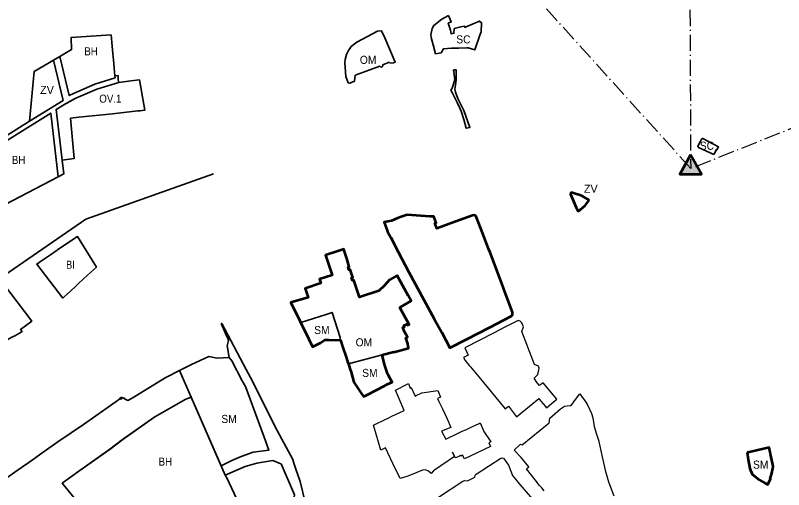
# Model space of a CAD drawing. Extents: x -650276 to -642489, y -1074311 to -1066658.
# Drawn here: x -648072 to -646929, y -1071077 to -1070373 of the extents above; entities that cross this region are included whole.
import ezdxf

# ---------------------------------------------------------------- set-up
doc = ezdxf.new("R2010")
doc.units = 0
doc.header["$LTSCALE"] = 4.8
doc.header["$PDMODE"] = 32
doc.header["$PDSIZE"] = 2.4
doc.linetypes.add('DOT_DASHED', pattern=[7.7, 5, -1.2, 0.3, -1.2])
for name, color, linetype, lineweight in [('1', 7, 'Continuous', 35), ('11', 7, 'Continuous', 35), ('12', 7, 'Continuous', 35), ('15', 7, 'Continuous', 35), ('17', 7, 'Continuous', 35), ('18', 7, 'Continuous', 35), ('2', 7, 'Continuous', 35), ('40', 7, 'Continuous', 35), ('54', 7, 'Continuous', 35), ('55', 7, 'Continuous', 53), ('60', 7, 'Continuous', 53), ('61', 7, 'Continuous', 25)]:
    doc.layers.add(name, color=color, linetype=linetype, lineweight=lineweight)
doc.layers.add('62', color=7, linetype='Continuous')
doc.layers.add('63', color=7, linetype='Continuous')

msp = doc.modelspace()

# ---------------------------------------------------------------- hatches: boundary and pattern name
at = {"layer": '55'}
msp.add_hatch(color=256, dxfattribs=at).paths.add_polyline_path([(-647067.857, -1070579.969), (-647083.808, -1070608.615), (-647051.424, -1070608.615)])

# ---------------------------------------------------------------- linework, layer by layer
at = {"layer": '1'}
for points in [[(-647991.539, -1070492.016), (-647985.19, -1070488.804), (-647953.251, -1070475.276), (-647923.247, -1070465.749), (-647923.53, -1070462.75), (-647924.63, -1070451.09), (-647925.5, -1070439.63), (-647926.53, -1070429.76), (-647927.67, -1070418.74), (-647929.24, -1070401.97), (-647988.86, -1070405.95), (-647988.11, -1070423.93), (-648005.668, -1070434.145)], [(-648098.637, -1070659.682), (-648007.838, -1070612.851), (-648019, -1070518), (-648135.47, -1070590.61), (-648105.98, -1070645.91)], [(-648001.922, -1071067.83), (-647977.41, -1071049.74), (-647930.7, -1071017.18), (-647911.838, -1071002.919), (-647864.03, -1070969.3), (-647864.03, -1070969.3), (-647818.33, -1070942.91), (-647810.243, -1070939.825), (-647759.52, -1071055.67), (-647757.19, -1071059.66), (-647742.64, -1071090.72), (-647726.74, -1071122.48), (-647742.35, -1071129.43), (-647775.982, -1071148.001), (-647775.982, -1071148.001), (-647875.939, -1071221.104)]]:
    msp.add_lwpolyline(points, close=True, dxfattribs=at)
at = {"layer": '11'}
msp.add_lwpolyline([(-647927.14, -1070519), (-647889.27, -1070514.92), (-647886.09, -1070514.58), (-647879.89, -1070513.91), (-647879.16, -1070513.83), (-647887.08, -1070468.54), (-647899.87, -1070470.04), (-647917.98, -1070472.47), (-647950.48, -1070482.79), (-647981.81, -1070496.06), (-647990.295, -1070500.352), (-647999.756, -1070505.655), (-648010.831, -1070512.588), (-648002, -1070588), (-647984.03, -1070585.46), (-647989.5, -1070525.73), (-647977.41, -1070524.43)], close=True, dxfattribs=at)
at = {"layer": '12'}
msp.add_lwpolyline([(-647515.73, -1070442.32), (-647514.23, -1070444.18), (-647509.22, -1070443.62), (-647506.95, -1070442.71), (-647522.54, -1070406.51), (-647527.1, -1070395.72), (-647533.1, -1070396.26), (-647564.01, -1070412.59), (-647572.37, -1070419.41), (-647576.48, -1070425.09), (-647579.22, -1070431.05), (-647581.04, -1070438.4), (-647581.54, -1070443.7), (-647580.1, -1070463.69), (-647576.92, -1070473), (-647574.28, -1070473.46), (-647567.32, -1070470.66), (-647566.55, -1070462.22), (-647565.11, -1070461.12), (-647529.74, -1070448.27), (-647528.28, -1070449.87), (-647525.54, -1070448.89), (-647525.45, -1070446.21)], close=True, dxfattribs=at)
msp.add_lwpolyline([(-647515.73, -1070442.32), (-647514.23, -1070444.18), (-647509.22, -1070443.62), (-647506.95, -1070442.71), (-647522.54, -1070406.51), (-647527.1, -1070395.72), (-647533.1, -1070396.26), (-647564.01, -1070412.59), (-647572.37, -1070419.41), (-647576.48, -1070425.09), (-647579.22, -1070431.05), (-647581.04, -1070438.4), (-647581.54, -1070443.7), (-647580.1, -1070463.69), (-647576.92, -1070473), (-647574.28, -1070473.46), (-647567.32, -1070470.66), (-647566.55, -1070462.22), (-647565.11, -1070461.12), (-647529.74, -1070448.27), (-647528.28, -1070449.87), (-647525.54, -1070448.89), (-647525.45, -1070446.21)], close=True, dxfattribs=at)
msp.add_lwpolyline([(-647515.73, -1070442.32), (-647514.23, -1070444.18), (-647509.22, -1070443.62), (-647506.95, -1070442.71), (-647522.54, -1070406.51), (-647527.1, -1070395.72), (-647533.1, -1070396.26), (-647564.01, -1070412.59), (-647572.37, -1070419.41), (-647576.48, -1070425.09), (-647579.22, -1070431.05), (-647581.04, -1070438.4), (-647581.54, -1070443.7), (-647580.1, -1070463.69), (-647576.92, -1070473), (-647574.28, -1070473.46), (-647567.32, -1070470.66), (-647566.55, -1070462.22), (-647565.11, -1070461.12), (-647529.74, -1070448.27), (-647528.28, -1070449.87), (-647525.54, -1070448.89), (-647525.45, -1070446.21)], close=True, dxfattribs=at)
for points in [[(-647569.92, -1070762.24), (-647573.88, -1070750.25), (-647575.58, -1070750.83), (-647576.81, -1070746.86), (-647575.09, -1070746.33), (-647578.79, -1070734.33), (-647583.38, -1070720.9), (-647583.22, -1070720.2), (-647593.6, -1070723.68), (-647610.33, -1070729.28), (-647600.53, -1070758.65), (-647619.2, -1070764.85), (-647617.36, -1070770.69)], [(-647636.12, -1070792.13), (-647654.89, -1070797.23), (-647662.26, -1070799.23), (-647650.908, -1070822.34), (-647647.405, -1070829.08), (-647609.58, -1070817.06), (-647600.8, -1070814.27), (-647588.89, -1070851.67), (-647588.4, -1070855.25), (-647584.6, -1070866.3), (-647580.22, -1070879.3), (-647578.703, -1070883.851), (-647578.703, -1070883.851), (-647576.469, -1070890.564), (-647526.13, -1070877.41), (-647509.1, -1070872.96), (-647508.96, -1070873.41), (-647487.16, -1070867.32), (-647487.91, -1070860.91), (-647490.92, -1070851.82), (-647488.8, -1070851.12), (-647494.1, -1070840.58), (-647495.93, -1070836.86), (-647493.16, -1070835.5), (-647494.03, -1070833.64), (-647489.55, -1070831.53), (-647488.75, -1070833.37), (-647485.9, -1070832), (-647500.07, -1070806.87), (-647500.07, -1070806.87), (-647483.16, -1070797.07), (-647492.81, -1070779.18), (-647492.81, -1070779.18), (-647497.227, -1070771.165), (-647503.76, -1070759.31), (-647514.49, -1070764.93), (-647517.61, -1070767.89), (-647523.07, -1070774.86), (-647531.05, -1070782.23), (-647560.06, -1070791.72), (-647566.26, -1070773.148)], [(-647570.27, -1070766.86), (-647571.63, -1070762.82), (-647569.92, -1070762.24)], [(-647566.26, -1070773.148), (-647568.55, -1070766.29), (-647570.27, -1070766.86)], [(-647617.36, -1070770.69), (-647619.12, -1070771.28), (-647640.66, -1070778.47), (-647636.12, -1070792.13)]]:
    msp.add_lwpolyline(points, dxfattribs=at)
at = {"layer": '15'}
for points in [[(-648007.838, -1070612.851), (-647999.588, -1070608.596), (-648002, -1070588), (-648010.831, -1070512.588), (-647999.756, -1070505.655), (-647981.81, -1070496.06), (-647950.48, -1070482.79), (-647917.98, -1070472.47), (-647918.54, -1070468.61), (-647918.95, -1070462.36), (-647923.53, -1070462.75), (-647923.247, -1070465.749), (-647953.251, -1070475.276), (-647985.19, -1070488.804), (-647991.539, -1070492.016), (-648005.668, -1070434.145), (-648014.63, -1070439.36), (-648000.442, -1070499.336), (-648019.789, -1070511.293), (-648050.38, -1070530.2), (-648122.57, -1070575), (-648137.78, -1070586.25), (-648135.47, -1070590.61), (-648019, -1070518)], [(-647404.96, -1070527.57), (-647401.35, -1070540.59), (-647395.75, -1070539.47), (-647404.879, -1070514.114), (-647413.552, -1070496.671), (-647417.297, -1070487.185), (-647418.038, -1070482.516), (-647417.482, -1070476.846), (-647416.37, -1070468.064), (-647416.148, -1070454.055), (-647418.49, -1070453.76), (-647420.13, -1070454.78), (-647420.22, -1070454.02), (-647418.41, -1070468.21), (-647420.74, -1070476.57), (-647422.285, -1070480.931), (-647424.226, -1070484.029), (-647422.19, -1070487.75), (-647414.6, -1070502.16), (-647410.86, -1070510.68), (-647408.82, -1070515.49)]]:
    msp.add_lwpolyline(points, close=True, dxfattribs=at)
for points in [[(-647659.01, -1071032.66), (-647685.1, -1070983.93), (-647719.06, -1070916.45), (-647728.35, -1070899.11), (-647764.84, -1070830.47), (-647765.72, -1070830.64)], [(-647765.72, -1070830.64), (-647759.08, -1070845.74), (-647755.87, -1070853.02), (-647754.6, -1070856.11), (-647756.45, -1070863.95), (-647753.81, -1070881.3)], [(-647753.81, -1070881.3), (-647749.75, -1070886.1), (-647734.48, -1070915.94), (-647729.27, -1070924.35), (-647701.45, -1070999.4)], [(-647701.45, -1070999.4), (-647694.54, -1071018.549), (-647718, -1071022), (-647736, -1071028), (-647750, -1071034), (-647765.408, -1071042.223), (-647759.52, -1071055.67), (-647730.17, -1071043.21), (-647712.74, -1071037.99), (-647688.9, -1071034.18), (-647676.96, -1071039.014)], [(-647676.96, -1071039.014), (-647676.9, -1071039.03), (-647676.45, -1071039.22), (-647656.443, -1071085.369), (-647658.55, -1071097.02), (-647669.02, -1071102.33), (-647667.35, -1071106.38), (-647655.47, -1071100.98), (-647640.727, -1071095.819)], [(-647640.727, -1071095.819), (-647648.106, -1071065.551), (-647654.747, -1071047.095), (-647657.699, -1071038.232), (-647659.01, -1071032.66)]]:
    msp.add_lwpolyline(points, dxfattribs=at)
at = {"layer": '17'}
for points in [[(-647427.8, -1070373.32), (-647437.76, -1070378.66), (-647449.69, -1070387.83), (-647452.17, -1070392.38), (-647453.71, -1070401.81), (-647453.35, -1070406.09), (-647450.51, -1070416.96), (-647446.93, -1070429.99), (-647438.45, -1070428.47), (-647434.85, -1070422.64), (-647423.38, -1070421.87), (-647412.51, -1070421.5), (-647400.41, -1070421.08), (-647398.21, -1070421.15), (-647388.6, -1070424.24), (-647381.11, -1070402.45), (-647379.3, -1070397.57), (-647378.49, -1070383.91), (-647381.65, -1070381.45), (-647400.22, -1070389.64), (-647403.27, -1070390.91), (-647404, -1070388.84), (-647409.36, -1070390.24), (-647419.08, -1070392.52), (-647419.68, -1070399.59), (-647423.58, -1070400.59), (-647424.54, -1070394.78), (-647425.99, -1070390.47), (-647427.96, -1070384.64), (-647423.57, -1070382.64)], [(-647033.01, -1070579.83), (-647029.44, -1070572.13), (-647028.52, -1070572.63), (-647026.14, -1070568.26), (-647049.52, -1070555.64), (-647050.37, -1070555.74), (-647051.14, -1070556.59), (-647052.77, -1070559.7), (-647056.79, -1070567.41), (-647056.8, -1070568.32), (-647055.79, -1070569.07)]]:
    msp.add_lwpolyline(points, close=True, dxfattribs=at)
at = {"layer": '18'}
for points in [[(-647588.4, -1070855.25), (-647588.89, -1070851.67), (-647600.8, -1070814.27), (-647609.58, -1070817.06), (-647647.405, -1070829.08)], [(-647647.405, -1070829.08), (-647635.11, -1070853.786), (-647629.92, -1070865.35), (-647618.01, -1070859.42), (-647611.3, -1070854.9), (-647605.64, -1070854.99), (-647588.4, -1070855.25)], [(-647511.37, -1070917.79), (-647516.66, -1070907.8), (-647518.12, -1070905.05), (-647522.74, -1070891.48), (-647526.13, -1070877.41), (-647576.469, -1070890.564)], [(-647576.469, -1070890.564), (-647576.43, -1070890.68), (-647575.35, -1070893.91), (-647574.09, -1070897.7), (-647572.32, -1070902.72), (-647568.2, -1070917.54), (-647556.52, -1070935.59), (-647553.94, -1070939.11)], [(-647553.94, -1070939.11), (-647553.94, -1070939.11), (-647550.59, -1070937.45), (-647533.31, -1070928.79), (-647518.35, -1070920.62)], [(-647518.35, -1070920.62), (-647514.7, -1070918.79), (-647511.37, -1070917.79)]]:
    msp.add_lwpolyline(points, dxfattribs=at)
for points in [[(-647736, -1071028), (-647718, -1071022), (-647694.54, -1071018.549), (-647701.45, -1070999.4), (-647729.27, -1070924.35), (-647734.48, -1070915.94), (-647749.75, -1070886.1), (-647753.81, -1070881.3), (-647771.47, -1070882.27), (-647783.95, -1070879.58), (-647809.74, -1070891.31), (-647827.527, -1070900.351), (-647810.243, -1070939.825), (-647765.408, -1071042.223), (-647750, -1071034)], [(-646983.66, -1071022.3), (-646982.08, -1071032.76), (-646979.75, -1071046.19), (-646976.03, -1071054.29), (-646965.69, -1071063.05), (-646956.66, -1071067.91), (-646952.75, -1071069.62), (-646948.83, -1071061.12), (-646949.48, -1071060.79), (-646947.41, -1071054.95), (-646945.38, -1071045.82), (-646944.88, -1071042.78), (-646948.89, -1071024.84), (-646949.39, -1071021.83), (-646951.06, -1071014.78), (-646955.09, -1071015.67)]]:
    msp.add_lwpolyline(points, close=True, dxfattribs=at)
at = {"layer": '2'}
for points in [[(-648032.601, -1070737.472), (-648039.82, -1070742.33), (-648000.85, -1070792.88), (-647999.06, -1070791.2), (-647994.63, -1070787.05), (-647994.63, -1070787.05), (-647982.89, -1070776.05), (-647976.97, -1070770.51), (-647964.21, -1070758.77), (-647951.11, -1070746.78), (-647979.17, -1070701.65), (-648008.28, -1070720.96), (-648009.29, -1070721.79), (-648019.49, -1070728.65)], [(-648114.77, -1070788.08), (-648125.2, -1070794.79), (-648083.65, -1070854.89), (-648076.73, -1070851.07), (-648074.41, -1070849.79), (-648072.59, -1070848.79), (-648065.35, -1070844.8), (-648061.52, -1070842.68), (-648063.76, -1070839.49), (-648056.61, -1070834.26), (-648047.17, -1070827.35), (-648089.27, -1070771.57), (-648104.78, -1070781.65)]]:
    msp.add_lwpolyline(points, close=True, dxfattribs=at)
msp.add_lwpolyline([(-647875.939, -1071221.104), (-648001.922, -1071067.83), (-647977.41, -1071049.74), (-647930.96, -1071017.383), (-647912.11, -1071003.11), (-647864.29, -1070969.503), (-647818.33, -1070942.91), (-647810.243, -1070939.825), (-647827.527, -1070900.351), (-647848.89, -1070911.21), (-647897.76, -1070941.62), (-647904.13, -1070944.78), (-647909.42, -1070942.63), (-647908.63, -1070942.1), (-647913.45, -1070940.79), (-647934.9, -1070955.87), (-647952.01, -1070967.82), (-647970.19, -1070980.45), (-647988.81, -1070993.27), (-648008.34, -1071006.32), (-648030.24, -1071021.91), (-648044.82, -1071032.25), (-648051.48, -1071036.97), (-648062.53, -1071044.59), (-648085.73, -1071060.92)], dxfattribs=at)
msp.add_point((-647914.73, -1070941.682), dxfattribs=at)
at = {"layer": '40'}
msp.add_lwpolyline([(-648014.63, -1070439.36), (-648000.442, -1070499.336), (-648050.38, -1070530.2), (-648043.43, -1070456.12)], close=True, dxfattribs=at)
for points in [[(-647218.44, -1070647.43), (-647229.34, -1070640.91), (-647243.28, -1070636.43), (-647245.6, -1070636.4), (-647246.49, -1070638.53), (-647241.89, -1070648.94)], [(-647241.89, -1070648.94), (-647237.61, -1070658.33), (-647235.02, -1070664.1), (-647227.76, -1070658.33)], [(-647227.76, -1070658.33), (-647224.57, -1070655.48), (-647224.37, -1070655.59), (-647218.44, -1070647.43)]]:
    msp.add_lwpolyline(points, dxfattribs=at)
at = {"layer": '54'}
msp.add_lwpolyline([(-648756.915, -1070932.76), (-648403.845, -1070737.419), (-648368.964, -1070716.905), (-648263.103, -1070807.79), (-648213.358, -1070823.563), (-648181.392, -1070823.076), (-647966.625, -1070675.686), (-647777.125, -1070608.309)], dxfattribs=at)
at = {"layer": '55', "linetype": 'DOT_DASHED', "lineweight": 25}
for p, q in [((-647072.859, -1069440.93), (-647067.564, -1070600.224)), ((-647067.564, -1070600.224), (-647577.112, -1070037.236)), ((-647060.176, -1070597.455), (-645765.418, -1070080.935))]:
    msp.add_line(p, q, dxfattribs=at)
at = {"layer": '55'}
msp.add_lwpolyline([(-647067.857, -1070579.969), (-647083.808, -1070608.615), (-647051.424, -1070608.615)], close=True, dxfattribs=at)
at = {"layer": '60'}
msp.add_line((-647235.02, -1070664.1), (-647227.76, -1070658.33), dxfattribs=at)
for points in [[(-647218.44, -1070647.43), (-647229.34, -1070640.91), (-647243.28, -1070636.43), (-647245.6, -1070636.4), (-647246.49, -1070638.53), (-647241.89, -1070648.94)], [(-647241.89, -1070648.94), (-647237.61, -1070658.33), (-647235.02, -1070664.1)], [(-647227.76, -1070658.33), (-647224.57, -1070655.48), (-647224.37, -1070655.59), (-647218.44, -1070647.43)]]:
    msp.add_lwpolyline(points, dxfattribs=at)
for points in [[(-647365.48, -1070835.85), (-647334.27, -1070819.86), (-647332.51, -1070817.97), (-647332.25, -1070813.72), (-647345.18, -1070779.89), (-647346.96, -1070775.41), (-647365.94, -1070725.08), (-647367.67, -1070720.73), (-647377.04, -1070696.22), (-647386.39, -1070671.74), (-647388.31, -1070669.95), (-647391.74, -1070670.16), (-647418.28, -1070679.89), (-647444.78, -1070689.6), (-647447.31, -1070682.72), (-647447.76, -1070681.5), (-647446.22, -1070680.91), (-647447.58, -1070677.36), (-647449.69, -1070671.81), (-647455.17, -1070671.48), (-647489.21, -1070669.41), (-647496.64, -1070671.93), (-647503.3, -1070674.3), (-647512.51, -1070677.98), (-647523.27, -1070680.11), (-647518.19, -1070693.93), (-647513.59, -1070702.8), (-647502.59, -1070724.13), (-647486.84, -1070754.54), (-647464.3, -1070795.6), (-647448.84, -1070823.79), (-647437.79, -1070844.12), (-647425.58, -1070866.7), (-647401.15, -1070854.25)], [(-647588.4, -1070855.25), (-647584.6, -1070866.3), (-647580.22, -1070879.3), (-647577.59, -1070887.19), (-647576.43, -1070890.68), (-647575.35, -1070893.91), (-647574.09, -1070897.7), (-647572.32, -1070902.72), (-647568.2, -1070917.54), (-647556.52, -1070935.59), (-647553.94, -1070939.11), (-647550.59, -1070937.45), (-647533.31, -1070928.79), (-647518.35, -1070920.62), (-647511.37, -1070917.79), (-647516.66, -1070907.8), (-647518.12, -1070905.05), (-647522.74, -1070891.48), (-647526.13, -1070877.41), (-647509.1, -1070872.96), (-647508.96, -1070873.41), (-647487.16, -1070867.32), (-647487.91, -1070860.91), (-647490.92, -1070851.82), (-647488.8, -1070851.12), (-647491.19, -1070846.49), (-647492.48, -1070843.88), (-647494.1, -1070840.58), (-647495.93, -1070836.86), (-647493.16, -1070835.5), (-647494.03, -1070833.64), (-647489.55, -1070831.53), (-647488.75, -1070833.37), (-647485.9, -1070832), (-647500.07, -1070806.87), (-647500.07, -1070806.87), (-647494.88, -1070803.86), (-647483.16, -1070797.07), (-647487.67, -1070788.86), (-647492.81, -1070779.18), (-647503.76, -1070759.31), (-647515.216, -1070765.619), (-647523.07, -1070774.86), (-647531.05, -1070782.23), (-647560.06, -1070791.72), (-647568.55, -1070766.29), (-647570.27, -1070766.86), (-647571.63, -1070762.82), (-647569.92, -1070762.24), (-647573.88, -1070750.25), (-647575.58, -1070750.83), (-647576.81, -1070746.86), (-647575.09, -1070746.33), (-647578.79, -1070734.33), (-647583.38, -1070720.9), (-647583.22, -1070720.2), (-647593.6, -1070723.68), (-647610.33, -1070729.28), (-647600.53, -1070758.65), (-647619.2, -1070764.85), (-647617.36, -1070770.69), (-647640.66, -1070778.47), (-647636.12, -1070792.13), (-647662.26, -1070799.23), (-647635.11, -1070853.786), (-647629.92, -1070865.35), (-647618.01, -1070859.42), (-647611.3, -1070854.9), (-647605.64, -1070854.99)], [(-646983.66, -1071022.3), (-646982.08, -1071032.76), (-646979.75, -1071046.19), (-646976.03, -1071054.29), (-646965.69, -1071063.05), (-646956.66, -1071067.91), (-646952.75, -1071069.62), (-646948.83, -1071061.12), (-646949.48, -1071060.79), (-646947.41, -1071054.95), (-646945.38, -1071045.82), (-646944.88, -1071042.78), (-646948.89, -1071024.84), (-646949.39, -1071021.83), (-646951.06, -1071014.78), (-646955.09, -1071015.67), (-646982.41, -1071022.23)]]:
    msp.add_lwpolyline(points, close=True, dxfattribs=at)
at = {"layer": '61'}
for points in [[(-647299.98, -1070891.49), (-647318.68, -1070842.72), (-647316.06, -1070835.75), (-647318.44, -1070829.76), (-647321.01, -1070827.14), (-647324.15, -1070826.29), (-647331.02, -1070829.74), (-647345.71, -1070837.13), (-647359.71, -1070844.27), (-647403.51, -1070866.6), (-647398.52, -1070877.49), (-647405.34, -1070881.23), (-647402.82, -1070885.66), (-647396.9, -1070892.8), (-647394.88, -1070895.23), (-647382.57, -1070910.05), (-647343.34, -1070957.27), (-647338.57, -1070953.63), (-647326.51, -1070969.42), (-647293.51, -1070942.01), (-647290.28, -1070945.89), (-647283.54, -1070954.02), (-647282.46, -1070955.31), (-647281.97, -1070955.9), (-647271.95, -1070947.47), (-647266.79, -1070942.95), (-647286.92, -1070918.59), (-647292.14, -1070922.88), (-647295.69, -1070918.55), (-647300.07, -1070911.99), (-647294.73, -1070906.32), (-647293.09, -1070897.18), (-647293.7, -1070893.99)], [(-647466.48, -1071048.33), (-647483.08, -1071055.41), (-647489.7, -1071057.66), (-647499.39, -1071060.95), (-647510.18, -1071038.65), (-647521.36, -1071015.52), (-647528.27, -1071018.94), (-647535.19, -1070995.23), (-647539.38, -1070981.6), (-647520.58, -1070972.61), (-647517.43, -1070971.1), (-647511.96, -1070968.48), (-647499.8, -1070962.67), (-647493.79, -1070959.8), (-647493.71, -1070959.89), (-647506.58, -1070929.86), (-647487.33, -1070919.95), (-647484.78, -1070926.54), (-647483.02, -1070925.66), (-647477.21, -1070938.44), (-647475.82, -1070937.77), (-647467.47, -1070933.53), (-647443.36, -1070930.41), (-647439.33, -1070940.28), (-647443.84, -1070942.26), (-647442.33, -1070945.38), (-647441.9, -1070946.28), (-647436.58, -1070957.29), (-647429.44, -1070972.06), (-647424.16, -1070985.19), (-647438.05, -1070990.74), (-647431.74, -1071002.56), (-647413.35, -1070993.67), (-647410.26, -1070992.23), (-647407.22, -1070990.81), (-647401.93, -1070988.34), (-647392.83, -1070984.14), (-647382.05, -1070979.01), (-647380.69, -1070978.37), (-647374.95, -1070991.15), (-647364.66, -1071006.25), (-647367.88, -1071007.78), (-647365.21, -1071013.19), (-647403.85, -1071031.66), (-647406.65, -1071026.24), (-647409.36, -1071027.52), (-647409.68, -1071026.85), (-647411.52, -1071027.64), (-647415.84, -1071029.49), (-647417.76, -1071030.31), (-647418.88, -1071028.01), (-647421.89, -1071021.82), (-647418.88, -1071028.01), (-647448.32, -1071048.39), (-647449.88, -1071049.31), (-647453.32, -1071053.37), (-647457.4, -1071049.84), (-647462.03, -1071047.83)]]:
    msp.add_lwpolyline(points, close=True, dxfattribs=at)
for points in [[(-647285.53, -1071079.39), (-647289.1, -1071074.88), (-647292.21, -1071071.21), (-647298.74, -1071062.85), (-647311.58, -1071046.44), (-647308, -1071043.56), (-647319.46, -1071029.7), (-647329.84, -1071018.95), (-647320.83, -1071009.87), (-647317.99, -1071010.98), (-647278.2, -1070978.19), (-647277.18, -1070971.26), (-647261.35, -1070957.45), (-647255.21, -1070953.46), (-647251.11, -1070953.01), (-647245.32, -1070952.38), (-647237.16, -1070941.5), (-647232.24, -1070934.94), (-647223.65, -1070947.55), (-647220.46, -1070952.68), (-647215.29, -1070964.36), (-647213.23, -1070970.92), (-647210.97, -1070983.56), (-647207.77, -1070995.03), (-647204.055, -1071005.609), (-647203.96, -1071005.88), (-647199.63, -1071026.94), (-647195.64, -1071044.04), (-647194.61, -1071048.68), (-647192.72, -1071055.27), (-647189.68, -1071065.99), (-647181.99, -1071086.74)], [(-647442.36, -1071088.82), (-647406.52, -1071065.05), (-647403.15, -1071063.6), (-647399.31, -1071064.09), (-647397.17, -1071063.56), (-647390.72, -1071059.94), (-647388.51, -1071058.82), (-647387.82, -1071056.14), (-647386.3, -1071054.58), (-647349.67, -1071030.64), (-647347.66, -1071030.16), (-647345.94, -1071030.88), (-647338.47, -1071040.94), (-647332.55, -1071056.58), (-647326.18, -1071064.18), (-647324.46, -1071066.41), (-647290.44, -1071106.08)]]:
    msp.add_lwpolyline(points, dxfattribs=at)

# ---------------------------------------------------------------- texts
at = {"layer": '62'}
for s, width, p in [('SC', 0.95, (-647416.06, -1070414.645)), ('BH', 0.9, (-647969.069, -1070432.39)), ('OM', 0.95, (-647559.43, -1070445.015)), ('OV.1', 0.9, (-647946.769, -1070502.709)), ('SC', 0.95, (-647054.06, -1070572.645)), ('BH', 0.9, (-648076.769, -1070593.709)), ('BI', 0.85, (-647996.127, -1070749.398)), ('SM', 0.95, (-647627.328, -1070846.374)), ('OM', 0.95, (-647565.708, -1070864.552)), ('SM', 0.95, (-647556.006, -1070910.054)), ('SM', 0.95, (-647765.328, -1070978.374)), ('BH', 0.9, (-647858.64, -1071041.819)), ('SM', 0.95, (-646974.938, -1071046.245))]:
    msp.add_text(s, height=12, dxfattribs=dict(at, width=width)).set_placement(p)
msp.add_text('ZV', height=12, dxfattribs=at).set_placement((-648034.769, -1070489.709))
at = {"layer": '63'}
msp.add_text('ZV', height=12, dxfattribs=at).set_placement((-647226.398, -1070636.507))

doc.saveas('drawing.dxf')
